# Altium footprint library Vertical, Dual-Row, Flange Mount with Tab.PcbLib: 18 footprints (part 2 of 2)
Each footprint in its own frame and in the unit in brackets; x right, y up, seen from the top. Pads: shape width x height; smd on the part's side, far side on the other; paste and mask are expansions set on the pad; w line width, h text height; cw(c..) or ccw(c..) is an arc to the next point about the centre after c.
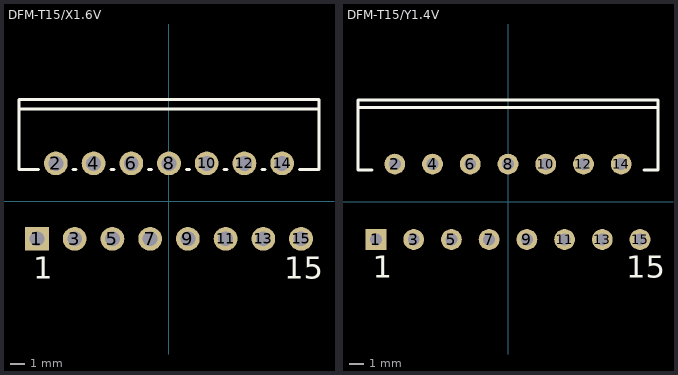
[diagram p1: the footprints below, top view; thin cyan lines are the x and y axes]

## DFM-T15/X1.6V [mm]
pads (15):
  rect 1.6x1.6 hole 1: 1(-8.89,-2.54)
  round 1.6 hole 1: 2(-7.62,2.54) 3(-6.35,-2.54) 4(-5.08,2.54) 5(-3.81,-2.54) 6(-2.54,2.54) 7(-1.27,-2.54) 8(0,2.54) 9(1.27,-2.54) 10(2.54,2.54) 11(3.81,-2.54) 12(5.08,2.54) 13(6.35,-2.54) 14(7.62,2.54) 15(8.89,-2.54)
Top Overlay:
  lines w0.2: -10.1,6.19 10.1,6.19 ; -8.8,2.14 -10.1,2.14 -10.1,6.84 10.1,6.84 10.1,2.14 8.8,2.14 ; -6.45,2.14 -6.25,2.14 ; -3.91,2.14 -3.71,2.14 ; -1.37,2.14 -1.17,2.14 ; 1.17,2.14 1.37,2.14 ; 3.71,2.14 3.91,2.14 ; 6.25,2.14 6.45,2.14
  text "15" at 7.765,-5.215 h1.5
  text "1" at -9.14,-5.215 h1.5

## DFM-T15/Y1.4V [mm]
pads (15):
  rect 1.4x1.4 hole 0.8: 1(-8.89,-2.54)
  round 1.4 hole 0.8: 2(-7.62,2.54) 3(-6.35,-2.54) 4(-5.08,2.54) 5(-3.81,-2.54) 6(-2.54,2.54) 7(-1.27,-2.54) 8(0,2.54) 9(1.27,-2.54) 10(2.54,2.54) 11(3.81,-2.54) 12(5.08,2.54) 13(6.35,-2.54) 14(7.62,2.54) 15(8.89,-2.54)
Top Overlay:
  lines w0.2: -10.1,6.34 10.1,6.34 ; -9.144,2.14 -10.1,2.14 -10.1,6.84 10.1,6.84 10.1,2.14 9.144,2.14
  text "15" at 7.95,-5.115 h1.5
  text "1" at -9.12,-5.115 h1.5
